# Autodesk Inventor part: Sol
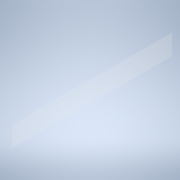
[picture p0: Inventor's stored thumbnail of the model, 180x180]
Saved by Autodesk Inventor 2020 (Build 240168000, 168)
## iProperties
Created: 2022-10
Part Number: Sol
Material: Générique
Document SubType Name: Modeling
Designer: bruno
Density: 1 g/cm^3
Appearance: Transparent - Clair
Author: bruno
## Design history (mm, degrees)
sketch "Esquisse1"
  geometry: L1 (0, 0)-(1000, 0); L2 (1000, 0)-(1000, -4000); L3 (1000, -4000)-(0, -4000); L4 (0, -4000)-(0, 0)
  constraints: 8 end point, 2 parallel, 1 horizontal, 1 perpendicular
  dimensions: "d0" = 1000 distance of L2.end L3.end; "d1" = 4000 distance of L1.end L2.end
extrude "Extrusion1" new body sketch "Esquisse1" distance "d2" = 10; taper "d3" = 0 deg
sketch "Esquisse2"
  geometry: L1 (-3773.641, 444.733)-(-3773.641, 488.483) reference; L2 (-3769.641, 491.608)-(-3773.641, 491.608) reference; C1 r 1.595 at (-3769.641, 491.608); 1 further point
  constraints: 1 centre point, 1 coincident
extrude "Extrusion2" join sketch "Esquisse2" distance "d4" = 150; taper "d5" = 0 deg
sketch "Esquisse3"
  geometry: L1 (10, 1000)-(10, 0) reference; L2 (0, 1000)-(0, 0) reference; L3 (0, 0)-(10, 0) reference; L4 (0, 1000)-(10, 1000) reference
extrude "Extrusion3" join sketch "Esquisse3" distance "d6" = 4000; taper "d7" = 0 deg
node "Solide1"
node "Référence1"
node "Référence2"
